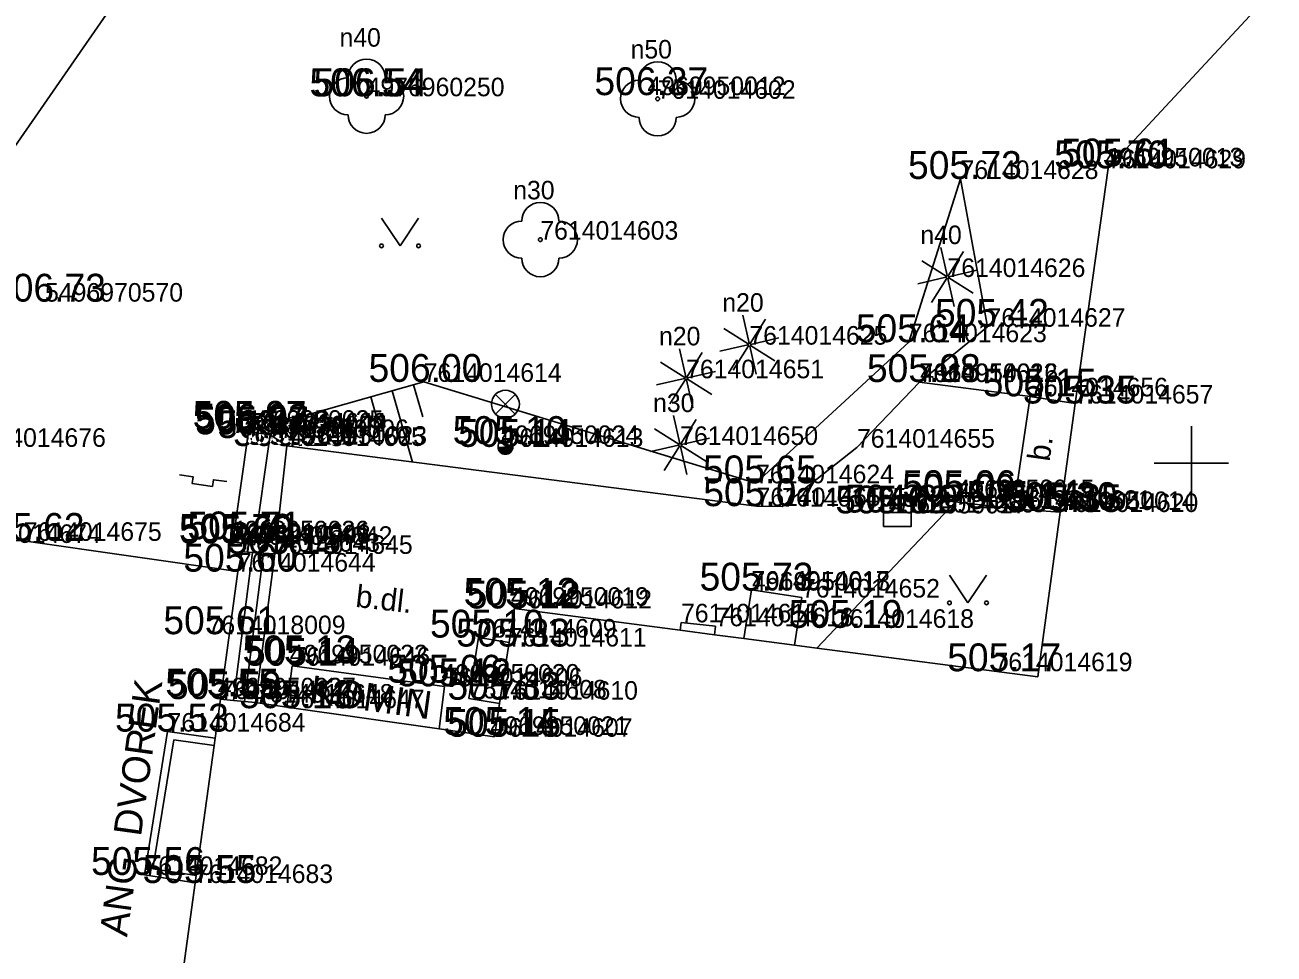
# Model space of a CAD drawing. Extents: x -669251 to -668549, y -1128351 to -1127698.
# Drawn here: x -668681.44 to -668647.77, y -1128063.22 to -1128038.19 of the extents above; entities that cross this region are included whole.
import ezdxf

# ---------------------------------------------------------------- set-up
doc = ezdxf.new("R2010")
doc.units = 0
for name, color, linetype in [('Vrstva 1', 7, 'Continuous'), ('Vrstva 10', 7, 'Continuous'), ('Vrstva 11', 7, 'Continuous'), ('Vrstva 14', 7, 'Continuous'), ('Vrstva 15', 7, 'Continuous'), ('Vrstva 2', 7, 'Continuous'), ('Vrstva 22', 7, 'Continuous'), ('Vrstva 24', 7, 'Continuous'), ('Vrstva 27', 7, 'Continuous'), ('Vrstva 3', 7, 'Continuous'), ('Vrstva 33', 7, 'Continuous'), ('Vrstva 36', 7, 'Continuous'), ('Vrstva 40', 7, 'Continuous'), ('Vrstva 42', 7, 'Continuous'), ('Vrstva 47', 7, 'Continuous'), ('Vrstva 5', 7, 'Continuous'), ('Vrstva 6', 7, 'Continuous'), ('Vrstva 61', 7, 'Continuous')]:
    doc.layers.add(name, color=color, linetype=linetype)

msp = doc.modelspace()

# ---------------------------------------------------------------- linework, layer by layer
at = {"layer": 'Vrstva 1'}
for p, q in [((-668672.23, -1128040.11), (-668672.23, -1128040.11)), ((-668664.66, -1128040.08), (-668664.66, -1128040.08)), ((-668664.385, -1128040.179), (-668664.385, -1128040.179)), ((-668652.32, -1128042), (-668652.32, -1128042)), ((-668652.247, -1128042.052), (-668652.247, -1128042.052)), ((-668656.223, -1128042.339), (-668656.223, -1128042.339)), ((-668667.548, -1128043.974), (-668667.548, -1128043.974)), ((-668656.575, -1128044.98), (-668656.575, -1128044.98)), ((-668680.895, -1128045.644), (-668680.895, -1128045.644)), ((-668655.495, -1128046.321), (-668655.495, -1128046.321)), ((-668661.913, -1128046.803), (-668661.913, -1128046.803)), ((-668657.616, -1128046.737), (-668657.616, -1128046.737)), ((-668670.691, -1128047.806), (-668670.691, -1128047.806)), ((-668663.619, -1128047.709), (-668663.619, -1128047.709)), ((-668657.33, -1128047.81), (-668657.33, -1128047.81)), ((-668657.31, -1128047.81), (-668657.31, -1128047.81)), ((-668654.35, -1128048.196), (-668654.35, -1128048.196)), ((-668653.129, -1128048.389), (-668653.129, -1128048.389)), ((-668675.5, -1128049.07), (-668675.5, -1128049.07)), ((-668675.42, -1128049.22), (-668675.42, -1128049.22)), ((-668675.412, -1128049.147), (-668675.412, -1128049.147)), ((-668675.411, -1128049.144), (-668675.411, -1128049.144)), ((-668674.81, -1128049.32), (-668674.81, -1128049.32)), ((-668674.377, -1128049.533), (-668674.377, -1128049.533)), ((-668674.32, -1128049.5), (-668674.32, -1128049.5)), ((-668668.6, -1128049.48), (-668668.6, -1128049.48)), ((-668668.488, -1128049.557), (-668668.488, -1128049.557)), ((-668663.779, -1128049.506), (-668663.779, -1128049.506)), ((-668659.014, -1128049.579), (-668659.014, -1128049.579)), ((-668661.735, -1128050.539), (-668661.735, -1128050.539)), ((-668656.33, -1128050.94), (-668656.33, -1128050.94)), ((-668661.72, -1128051.155), (-668661.72, -1128051.155)), ((-668661.03, -1128051.167), (-668661.03, -1128051.167)), ((-668658.16, -1128051.35), (-668658.16, -1128051.35)), ((-668657.926, -1128051.327), (-668657.926, -1128051.327)), ((-668656.36, -1128051.041), (-668656.36, -1128051.041)), ((-668654.791, -1128051.228), (-668654.791, -1128051.228)), ((-668653.61, -1128051.26), (-668653.61, -1128051.26)), ((-668653.534, -1128051.313), (-668653.534, -1128051.313)), ((-668675.88, -1128052.05), (-668675.88, -1128052.05)), ((-668675.84, -1128052.16), (-668675.84, -1128052.16)), ((-668675.837, -1128052.112), (-668675.837, -1128052.112)), ((-668675.252, -1128052.198), (-668675.252, -1128052.198)), ((-668675.586, -1128052.384), (-668675.586, -1128052.384)), ((-668674.706, -1128052.441), (-668674.706, -1128052.441)), ((-668675.704, -1128052.919), (-668675.704, -1128052.919)), ((-668661.856, -1128053.406), (-668661.856, -1128053.406)), ((-668661.84, -1128053.43), (-668661.84, -1128053.43)), ((-668660.496, -1128053.618), (-668660.496, -1128053.618)), ((-668668.34, -1128053.84), (-668668.34, -1128053.84)), ((-668668.256, -1128053.912), (-668668.256, -1128053.912)), ((-668663.756, -1128054.286), (-668663.756, -1128054.286)), ((-668676.515, -1128054.605), (-668676.515, -1128054.605)), ((-668669.212, -1128054.696), (-668669.212, -1128054.696)), ((-668662.824, -1128054.392), (-668662.824, -1128054.392)), ((-668659.579, -1128054.434), (-668659.579, -1128054.434)), ((-668668.401, -1128054.938), (-668668.401, -1128054.938)), ((-668674.3, -1128055.39), (-668674.3, -1128055.39)), ((-668674.232, -1128055.454), (-668674.232, -1128055.454)), ((-668655.307, -1128055.603), (-668655.307, -1128055.603)), ((-668670.21, -1128055.91), (-668670.21, -1128055.91)), ((-668670.13, -1128056.01), (-668670.13, -1128056.01)), ((-668676.24, -1128056.28), (-668676.24, -1128056.28)), ((-668676.166, -1128056.354), (-668676.166, -1128056.354)), ((-668669.475, -1128056.337), (-668669.475, -1128056.337)), ((-668668.635, -1128056.37), (-668668.635, -1128056.37)), ((-668675.223, -1128056.45), (-668675.223, -1128056.45)), ((-668674.386, -1128056.599), (-668674.386, -1128056.599)), ((-668677.594, -1128057.23), (-668677.594, -1128057.23)), ((-668668.89, -1128057.32), (-668668.89, -1128057.32)), ((-668668.781, -1128057.368), (-668668.781, -1128057.368)), ((-668678.217, -1128061.093), (-668678.217, -1128061.093)), ((-668676.851, -1128061.309), (-668676.851, -1128061.309))]:
    msp.add_line(p, q, dxfattribs=at)
at = {"layer": 'Vrstva 10'}
for p, q in [((-668668.403, -1128022.291), (-668686.448, -1128048.279)), ((-668659.014, -1128049.579), (-668657.33, -1128047.81)), ((-668657.33, -1128047.81), (-668654.35, -1128048.196)), ((-668654.35, -1128048.196), (-668653.129, -1128048.389)), ((-668674.706, -1128052.441), (-668674.377, -1128049.533)), ((-668674.377, -1128049.533), (-668661.72, -1128051.155)), ((-668661.03, -1128051.167), (-668659.014, -1128049.579)), ((-668661.72, -1128051.155), (-668661.03, -1128051.167)), ((-668660.095, -1128054.978), (-668656.36, -1128051.041)), ((-668656.36, -1128051.041), (-668654.791, -1128051.228)), ((-668654.791, -1128051.228), (-668653.534, -1128051.313))]:
    msp.add_line(p, q, dxfattribs=at)
msp.add_lwpolyline([(-668683.719, -1128052.297), (-668683.111, -1128052.146), (-668682.289, -1128052.058), (-668681.47, -1128052.09), (-668678.587, -1128052.505), (-668675.704, -1128052.919)], dxfattribs=at)
at = {"layer": 'Vrstva 11'}
for p, q in [((-668654.791, -1128051.228), (-668654.35, -1128048.196)), ((-668675.306, -1128052.402), (-668675.82, -1128056.389)), ((-668675.586, -1128052.384), (-668675.306, -1128052.402)), ((-668675.006, -1128052.422), (-668675.522, -1128056.42)), ((-668675.306, -1128052.402), (-668675.006, -1128052.422)), ((-668674.706, -1128052.441), (-668675.223, -1128056.45)), ((-668675.006, -1128052.422), (-668674.706, -1128052.441)), ((-668662.061, -1128054.721), (-668661.856, -1128053.406)), ((-668661.856, -1128053.406), (-668660.496, -1128053.618)), ((-668660.696, -1128054.899), (-668660.496, -1128053.618)), ((-668663.78, -1128054.497), (-668663.756, -1128054.286)), ((-668663.756, -1128054.286), (-668662.824, -1128054.392)), ((-668669.212, -1128054.696), (-668669.475, -1128056.337)), ((-668668.385, -1128054.828), (-668669.212, -1128054.696)), ((-668662.85, -1128054.618), (-668662.824, -1128054.392)), ((-668674.382, -1128056.57), (-668674.232, -1128055.454)), ((-668674.232, -1128055.454), (-668670.13, -1128056.01)), ((-668670.13, -1128056.01), (-668670.27, -1128057.156)), ((-668668.649, -1128056.469), (-668669.475, -1128056.337)), ((-668677.594, -1128057.23), (-668678.217, -1128061.093)), ((-668676.312, -1128057.407), (-668677.594, -1128057.23)), ((-668677.428, -1128057.455), (-668677.988, -1128060.927)), ((-668676.339, -1128057.605), (-668677.428, -1128057.455)), ((-668676.851, -1128061.309), (-668678.217, -1128061.093)), ((-668676.824, -1128061.111), (-668677.988, -1128060.927))]:
    msp.add_line(p, q, dxfattribs=at)
msp.add_lwpolyline([(-668676.166, -1128056.354), (-668675.704, -1128052.919), (-668675.586, -1128052.384)], dxfattribs=at)
at = {"layer": 'Vrstva 14'}
for p, q in [((-668657.616, -1128046.737), (-668656.223, -1128042.339)), ((-668656.223, -1128042.339), (-668655.495, -1128046.321)), ((-668655.495, -1128046.321), (-668657.33, -1128047.81)), ((-668661.735, -1128050.539), (-668657.616, -1128046.737)), ((-668675.412, -1128049.147), (-668670.691, -1128047.806)), ((-668670.691, -1128047.806), (-668661.735, -1128050.539)), ((-668674.827, -1128049.233), (-668674.377, -1128049.533))]:
    msp.add_line(p, q, dxfattribs=at)
at = {"layer": 'Vrstva 15'}
for p, q in [((-668670.962, -1128047.883), (-668670.716, -1128048.75)), ((-668672.117, -1128048.211), (-668671.926, -1128048.88)), ((-668671.539, -1128048.047), (-668670.994, -1128049.966))]:
    msp.add_line(p, q, dxfattribs=at)
at = {"layer": 'Vrstva 22'}
for p, q in [((-668656.583, -1128044.94), (-668656.755, -1128044.186)), ((-668656.141, -1128044.29), (-668656.555, -1128044.946)), ((-668656.609, -1128044.96), (-668657.265, -1128044.546)), ((-668656.535, -1128044.972), (-668655.781, -1128044.8)), ((-668657.369, -1128045.16), (-668656.615, -1128044.988)), ((-668656.595, -1128045.014), (-668657.009, -1128045.67)), ((-668656.567, -1128045.02), (-668656.395, -1128045.774)), ((-668655.885, -1128045.414), (-668656.541, -1128045)), ((-668661.921, -1128046.763), (-668662.093, -1128046.009)), ((-668661.479, -1128046.113), (-668661.893, -1128046.769)), ((-668661.947, -1128046.783), (-668662.603, -1128046.369)), ((-668661.873, -1128046.795), (-668661.119, -1128046.623)), ((-668663.627, -1128047.669), (-668663.799, -1128046.915)), ((-668662.707, -1128046.983), (-668661.953, -1128046.811)), ((-668661.933, -1128046.837), (-668662.347, -1128047.493)), ((-668661.905, -1128046.843), (-668661.733, -1128047.597)), ((-668661.223, -1128047.237), (-668661.879, -1128046.823)), ((-668663.653, -1128047.689), (-668664.309, -1128047.275)), ((-668663.185, -1128047.019), (-668663.599, -1128047.675)), ((-668663.579, -1128047.701), (-668662.825, -1128047.529)), ((-668664.413, -1128047.889), (-668663.659, -1128047.717)), ((-668663.639, -1128047.743), (-668664.053, -1128048.399)), ((-668663.611, -1128047.749), (-668663.439, -1128048.503)), ((-668662.929, -1128048.143), (-668663.585, -1128047.729)), ((-668663.787, -1128049.466), (-668663.959, -1128048.712)), ((-668663.345, -1128048.816), (-668663.759, -1128049.472)), ((-668663.813, -1128049.486), (-668664.469, -1128049.072)), ((-668663.739, -1128049.498), (-668662.985, -1128049.326)), ((-668664.573, -1128049.686), (-668663.819, -1128049.514)), ((-668663.799, -1128049.54), (-668664.213, -1128050.196)), ((-668663.771, -1128049.546), (-668663.599, -1128050.3)), ((-668663.089, -1128049.94), (-668663.745, -1128049.526))]:
    msp.add_line(p, q, dxfattribs=at)
for centre, radius in [((-668672.23, -1128040.11), 0.05), ((-668664.385, -1128040.179), 0.05), ((-668667.548, -1128043.974), 0.05), ((-668656.575, -1128044.98), 0.04), ((-668661.913, -1128046.803), 0.04), ((-668663.619, -1128047.709), 0.04), ((-668663.779, -1128049.506), 0.04)]:
    msp.add_circle(centre, radius, dxfattribs=at)
for centre, start, end in [((-668672.23, -1128039.61), 0, 180), ((-668664.385, -1128039.679), 0, 180), ((-668672.73, -1128040.11), 90, 270), ((-668671.73, -1128040.11), 270, 90), ((-668664.885, -1128040.179), 90, 270), ((-668663.885, -1128040.179), 270, 90), ((-668672.23, -1128040.61), 180, 0), ((-668664.385, -1128040.679), 180, 0), ((-668667.548, -1128043.474), 0, 180), ((-668668.048, -1128043.974), 90, 270), ((-668667.048, -1128043.974), 270, 90), ((-668667.548, -1128044.474), 180, 0)]:
    msp.add_arc(centre, 0.5, start, end, dxfattribs=at)
at = {"layer": 'Vrstva 24'}
for p, q in [((-668675.837, -1128052.112), (-668675.411, -1128049.144)), ((-668674.827, -1128049.233), (-668675.411, -1128049.147)), ((-668675.252, -1128052.198), (-668674.827, -1128049.233)), ((-668675.837, -1128052.112), (-668675.252, -1128052.198))]:
    msp.add_line(p, q, dxfattribs=at)
msp.add_lwpolyline([(-668677.27, -1128050.31), (-668676.906, -1128050.363), (-668676.932, -1128050.544), (-668676.386, -1128050.623), (-668676.359, -1128050.442), (-668675.994, -1128050.493)], dxfattribs=at)
at = {"layer": 'Vrstva 27'}
msp.add_line((-668658.301, -1128051.327), (-668657.551, -1128051.327), dxfattribs=at)
msp.add_lwpolyline([(-668658.301, -1128051.701), (-668657.551, -1128051.701), (-668657.551, -1128050.951), (-668658.301, -1128050.951)], close=True, dxfattribs=at)
at = {"layer": 'Vrstva 33'}
for p, q in [((-668668.753, -1128048.142), (-668668.223, -1128048.672)), ((-668668.753, -1128048.672), (-668668.223, -1128048.142)), ((-668668.488, -1128049.557), (-668668.488, -1128048.782))]:
    msp.add_line(p, q, dxfattribs=at)
for centre, radius in [((-668668.488, -1128048.407), 0.375), ((-668668.488, -1128049.557), 0.2)]:
    msp.add_circle(centre, radius, dxfattribs=at)
for radius in [0.18, 0.16, 0.14, 0.12, 0.1, 0.08, 0.06, 0.04, 0.02]:
    msp.add_arc((-668668.488, -1128049.557), radius, 180, 0, dxfattribs=at)
at = {"layer": 'Vrstva 36'}
for p, q in [((-668671.828, -1128043.393), (-668671.328, -1128044.143)), ((-668671.328, -1128044.143), (-668670.828, -1128043.393)), ((-668656.523, -1128053.011), (-668656.023, -1128053.761)), ((-668656.023, -1128053.761), (-668655.523, -1128053.011))]:
    msp.add_line(p, q, dxfattribs=at)
for centre in [(-668671.828, -1128044.143), (-668670.828, -1128044.143), (-668656.523, -1128053.761), (-668655.523, -1128053.761)]:
    msp.add_circle(centre, 0.05, dxfattribs=at)
at = {"layer": 'Vrstva 5'}
for p, q in [((-668652.247, -1128042.052), (-668641.364, -1128030.347)), ((-668652.247, -1128042.052), (-668653.129, -1128048.389)), ((-668653.534, -1128051.313), (-668654.137, -1128055.756)), ((-668668.385, -1128054.828), (-668668.256, -1128053.912)), ((-668668.256, -1128053.912), (-668663.78, -1128054.497)), ((-668663.78, -1128054.497), (-668662.85, -1128054.618)), ((-668662.85, -1128054.618), (-668662.061, -1128054.721)), ((-668662.061, -1128054.721), (-668660.696, -1128054.899)), ((-668668.401, -1128054.938), (-668668.385, -1128054.828)), ((-668660.696, -1128054.899), (-668660.095, -1128054.978)), ((-668660.095, -1128054.978), (-668654.137, -1128055.756)), ((-668676.312, -1128057.407), (-668676.166, -1128056.354)), ((-668668.781, -1128057.368), (-668668.649, -1128056.469)), ((-668676.339, -1128057.605), (-668676.312, -1128057.407)), ((-668676.824, -1128061.111), (-668676.339, -1128057.605)), ((-668676.851, -1128061.309), (-668676.824, -1128061.111)), ((-668678.169, -1128070.873), (-668676.851, -1128061.309))]:
    msp.add_line(p, q, dxfattribs=at)
for points in [[(-668676.166, -1128056.354), (-668675.82, -1128056.389)], [(-668675.82, -1128056.389), (-668675.522, -1128056.42)], [(-668675.522, -1128056.42), (-668675.223, -1128056.45), (-668674.382, -1128056.57)], [(-668674.382, -1128056.57), (-668670.27, -1128057.156)], [(-668670.27, -1128057.156), (-668668.781, -1128057.368)]]:
    msp.add_lwpolyline(points, dxfattribs=at)
at = {"layer": 'Vrstva 6'}
for p, q in [((-668653.129, -1128048.389), (-668653.534, -1128051.313)), ((-668668.401, -1128054.938), (-668668.649, -1128056.469))]:
    msp.add_line(p, q, dxfattribs=at)
at = {"layer": 'Vrstva 61'}
for p, q in [((-668650, -1128049), (-668650, -1128051)), ((-668651, -1128050), (-668649, -1128050))]:
    msp.add_line(p, q, dxfattribs=at)

# ---------------------------------------------------------------- texts
at = {"layer": 'Vrstva 2'}
for s, p in [('4969950012', (-668664.66, -1128040.08)), ('4976960250', (-668672.23, -1128040.11)), ('7614014602', (-668664.385, -1128040.179)), ('4969950013', (-668652.32, -1128042)), ('7614014629', (-668652.247, -1128042.052)), ('7614014628', (-668656.223, -1128042.339)), ('7614014603', (-668667.548, -1128043.974)), ('7614014626', (-668656.575, -1128044.98)), ('5496970570', (-668680.895, -1128045.644)), ('7614014627', (-668655.495, -1128046.321)), ('7614014625', (-668661.913, -1128046.803)), ('7614014623', (-668657.616, -1128046.737)), ('7614014614', (-668670.691, -1128047.806)), ('7614014651', (-668663.619, -1128047.709)), ('7614014622', (-668657.33, -1128047.81)), ('4969950016', (-668657.31, -1128047.81)), ('7614014656', (-668654.35, -1128048.196)), ('7614014657', (-668653.129, -1128048.389)), ('4969950025', (-668675.5, -1128049.07)), ('7614014640', (-668675.412, -1128049.147)), ('7614014604', (-668675.411, -1128049.144)), ('4335930007', (-668675.42, -1128049.22)), ('4335930006', (-668674.81, -1128049.32)), ('4969950023', (-668674.32, -1128049.5)), ('4969950024', (-668668.6, -1128049.48)), ('7614014650', (-668663.779, -1128049.506)), ('7614014676', (-668682.975, -1128049.557)), ('7614014605', (-668674.377, -1128049.533)), ('7614014613', (-668668.488, -1128049.557)), ('7614014655', (-668659.014, -1128049.579)), ('7614014624', (-668661.735, -1128050.539)), ('7614014653', (-668661.72, -1128051.155)), ('7614014654', (-668661.03, -1128051.167)), ('7614014658', (-668656.36, -1128051.041)), ('4969950015', (-668656.33, -1128050.94)), ('4969950017', (-668658.16, -1128051.35)), ('7614014659', (-668657.926, -1128051.327)), ('7614014621', (-668654.791, -1128051.228)), ('4969950014', (-668653.61, -1128051.26)), ('7614014620', (-668653.534, -1128051.313)), ('7614014674', (-668683.111, -1128052.146)), ('7614014675', (-668681.47, -1128052.09)), ('4969950026', (-668675.88, -1128052.05)), ('4335930008', (-668675.84, -1128052.16)), ('7614014641', (-668675.837, -1128052.112)), ('7614014642', (-668675.252, -1128052.198)), ('7614014643', (-668675.586, -1128052.384)), ('7614014645', (-668674.706, -1128052.441)), ('7614014644', (-668675.704, -1128052.919)), ('4969950018', (-668661.84, -1128053.43)), ('7614014617', (-668661.856, -1128053.406)), ('4969950019', (-668668.34, -1128053.84)), ('7614014652', (-668660.496, -1128053.618)), ('7614014612', (-668668.256, -1128053.912)), ('7614014615', (-668663.756, -1128054.286)), ('7614014616', (-668662.824, -1128054.392)), ('7614014618', (-668659.579, -1128054.434)), ('7614018009', (-668676.515, -1128054.605)), ('7614014609', (-668669.212, -1128054.696)), ('7614014611', (-668668.401, -1128054.938)), ('4969950022', (-668674.3, -1128055.39)), ('7614014646', (-668674.232, -1128055.454)), ('7614014619', (-668655.307, -1128055.603)), ('4969950020', (-668670.21, -1128055.91)), ('7614014606', (-668670.13, -1128056.01)), ('4969950027', (-668676.24, -1128056.28)), ('7614014649', (-668676.166, -1128056.354)), ('7614014648', (-668675.223, -1128056.45)), ('7614014608', (-668669.475, -1128056.337)), ('7614014610', (-668668.635, -1128056.37)), ('7614014647', (-668674.386, -1128056.599)), ('7614014684', (-668677.594, -1128057.23)), ('4969950021', (-668668.89, -1128057.32)), ('7614014607', (-668668.781, -1128057.368)), ('7614014682', (-668678.217, -1128061.093)), ('7614014683', (-668676.851, -1128061.309))]:
    msp.add_text(s, height=0.5, dxfattribs=at).set_placement(p)
at = {"layer": 'Vrstva 3'}
for s, p in [('506.54 ', (-668673.769, -1128040.11)), ('506.54 ', (-668673.659, -1128040.11)), ('506.37 ', (-668666.089, -1128040.08)), ('505.61 ', (-668653.512, -1128042)), ('505.73 ', (-668657.638, -1128042.339)), ('505.70 ', (-668653.698, -1128042.052)), ('506.73 ', (-668682.324, -1128045.644)), ('505.42 ', (-668656.91, -1128046.321)), ('505.64 ', (-668659.045, -1128046.737)), ('506.00 ', (-668672.177, -1128047.806)), ('505.08 ', (-668658.746, -1128047.81)), ('505.23 ', (-668658.745, -1128047.81)), ('505.15 ', (-668655.624, -1128048.196)), ('505.35 ', (-668654.544, -1128048.389)), ('505.97 ', (-668676.917, -1128049.07)), ('506.03 ', (-668676.862, -1128049.147)), ('506.02 ', (-668676.861, -1128049.144)), ('505.67 ', (-668676.849, -1128049.22)), ('505.46 ', (-668676.248, -1128049.32)), ('505.20 ', (-668675.828, -1128049.533)), ('505.21 ', (-668675.498, -1128049.5)), ('505.10 ', (-668669.909, -1128049.48)), ('505.14 ', (-668669.762, -1128049.557)), ('505.65 ', (-668663.164, -1128050.539)), ('505.09 ', (-668657.8, -1128051.041)), ('505.06 ', (-668657.79, -1128050.94)), ('505.07 ', (-668663.156, -1128051.155)), ('505.02 ', (-668659.596, -1128051.35)), ('504.89 ', (-668659.344, -1128051.327)), ('505.14 ', (-668656.065, -1128051.228)), ('505.30 ', (-668655.061, -1128051.26)), ('505.35 ', (-668654.949, -1128051.313)), ('505.62 ', (-668682.899, -1128052.09)), ('505.70 ', (-668677.288, -1128052.112)), ('505.71 ', (-668677.058, -1128052.05)), ('505.69 ', (-668677.272, -1128052.16)), ('505.15 ', (-668675.98, -1128052.441)), ('505.60 ', (-668677.168, -1128052.919)), ('505.73 ', (-668663.255, -1128053.43)), ('505.12 ', (-668669.614, -1128053.84)), ('505.12 ', (-668669.53, -1128053.912)), ('505.19 ', (-668660.855, -1128054.434)), ('505.61 ', (-668677.707, -1128054.605)), ('505.10 ', (-668670.521, -1128054.696)), ('505.33 ', (-668669.816, -1128054.938)), ('505.13 ', (-668675.574, -1128055.39)), ('505.14 ', (-668675.506, -1128055.454)), ('505.17 ', (-668656.581, -1128055.603)), ('505.06 ', (-668671.67, -1128055.91)), ('505.12 ', (-668671.404, -1128056.01)), ('505.55 ', (-668677.655, -1128056.28)), ('505.59 ', (-668677.584, -1128056.354)), ('505.33 ', (-668670.05, -1128056.37)), ('505.13 ', (-668675.66, -1128056.599)), ('505.53 ', (-668679.009, -1128057.23)), ('505.14 ', (-668670.164, -1128057.32)), ('505.15 ', (-668670.055, -1128057.368)), ('505.56 ', (-668679.655, -1128061.093)), ('505.55 ', (-668678.266, -1128061.309))]:
    msp.add_text(s, height=0.75, dxfattribs=at).set_placement(p)
at = {"layer": 'Vrstva 40'}
for s, rotation, p in [('b.', 82.1142, (-668653.824, -1128049.968)), ('b.dl.', 353.4637, (-668672.545, -1128053.867)), ('b.', 80.7194, (-668668.697, -1128055.874))]:
    msp.add_text(s, height=0.6, rotation=rotation, dxfattribs=at).set_placement(p)
at = {"layer": 'Vrstva 42'}
for s, rotation, p in [('KOMÍN', 352.1819, (-668673.789, -1128056.451)), ('ANG. DVOREK', 82.1291, (-668678.685, -1128062.779))]:
    msp.add_text(s, height=0.75, rotation=rotation, dxfattribs=at).set_placement(p)
at = {"layer": 'Vrstva 47'}
for s, height, p in [('n40', 0.499, (-668672.959, -1128038.774)), ('n50', 0.499, (-668665.114, -1128039.093)), ('n30', 0.499, (-668668.277, -1128042.888)), ('n40', 0.5, (-668657.305, -1128044.094)), ('n20', 0.5, (-668662.643, -1128045.917)), ('n20', 0.5, (-668664.349, -1128046.823)), ('n30', 0.5, (-668664.509, -1128048.62))]:
    msp.add_text(s, height=height, dxfattribs=at).set_placement(p)

doc.saveas('drawing.dxf')
